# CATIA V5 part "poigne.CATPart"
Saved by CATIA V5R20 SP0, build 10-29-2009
Part number: poine
Bounding box of the stored display mesh (mm): x -9.821 to 9.821, y -9.821 to 9.821, z 0 to 16.807
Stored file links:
  C:\Users\bensf\Desktop\bouthaina\poigne.CATPart
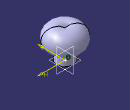
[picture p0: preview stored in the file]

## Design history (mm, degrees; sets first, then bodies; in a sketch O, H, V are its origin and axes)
Body1 (main body)
  Sketch1 on zx-plane, origin (0, 0, 0), H (-1, 0, 0), V (0, 0, 1)
    line L1 (0, 0) -> (0, 15.5327)
    point P1 (0, 15.5327)
    line L2 (0, 0) -> (4.5529, 0)
    line L3 (4.5529, 0) -> (4.5529, 5)
    arc A1 centre (3.8883, 10.9631) radius 6 from (4.5529, 5) to (0, 15.5327) ccw
    point P5 (0, 15.5327)
    radius A1 = 6
    length L3 = 5
    vertical: L1 V, L3 V
    horizontal: L2 H
    coincidence: A1 P1, P5 V, P1 P5
  Shaft1: profile Sketch1, axis Sketch1.L1, angle 360
  Sketch2 on face of Shaft1 from Sketch1.L2, origin (0, 0, 0), H (1, 0, 0), V (0, -1, 0)
    point P1 (0, 0)
    coincidence: P1 O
